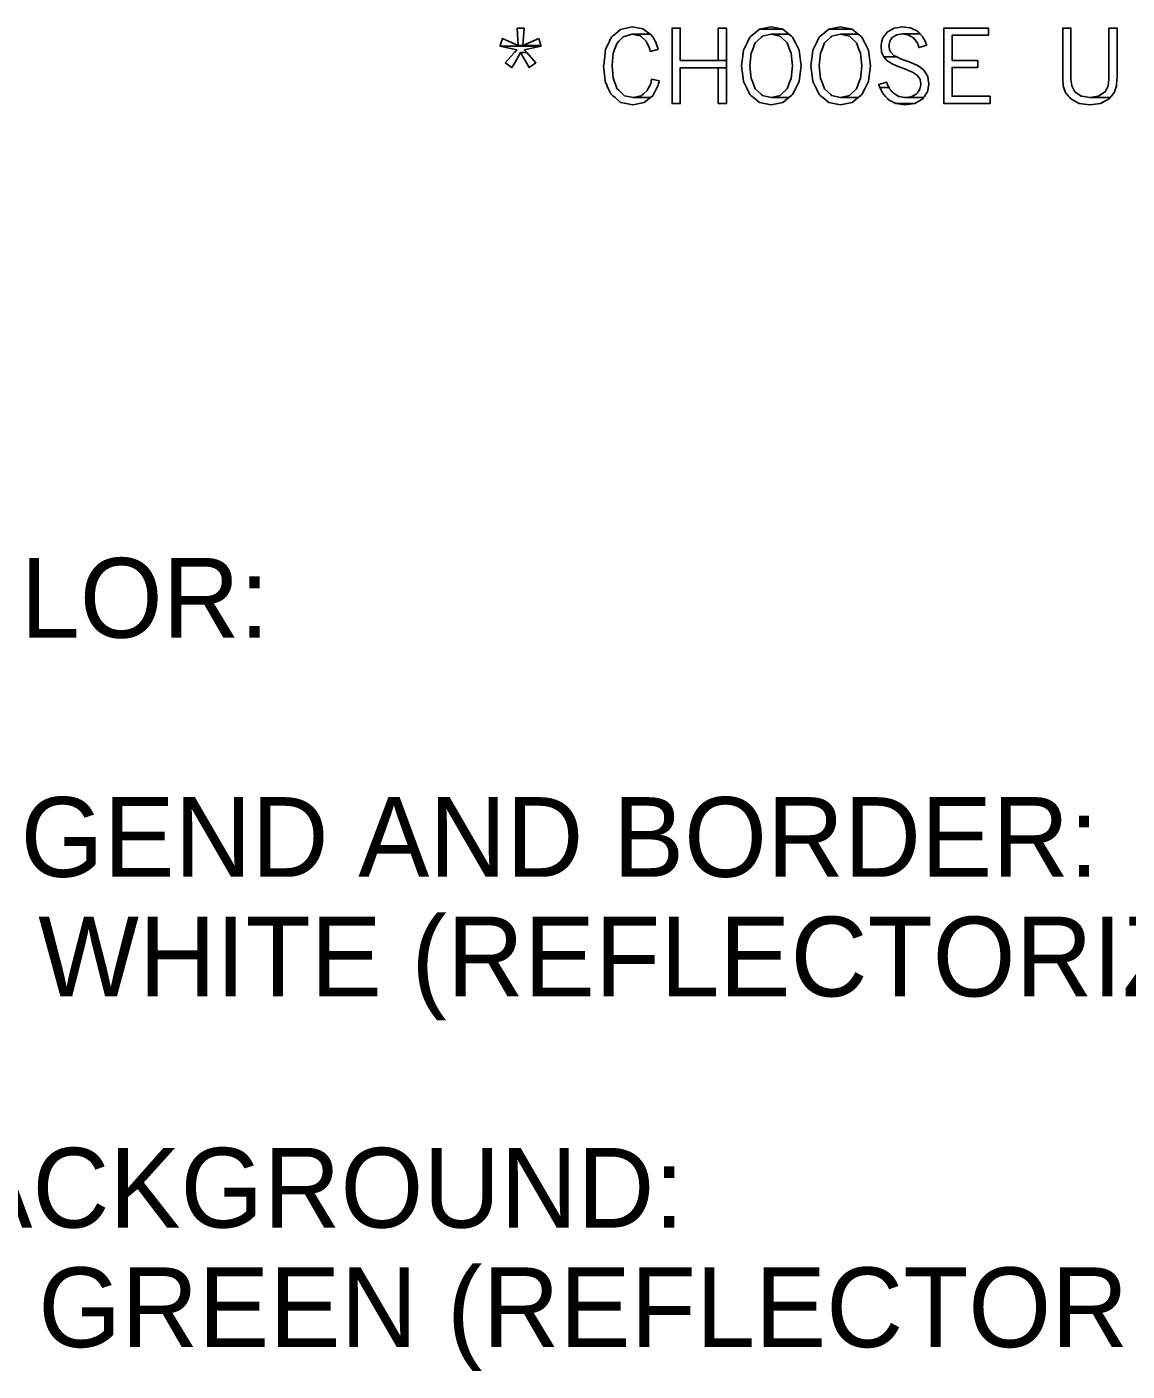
# Model space of a CAD drawing. Extents: x 0.011 to 0.188, y 0.004 to 0.261.
# Drawn here: x 0.02906 to 0.06383, y 0.00969 to 0.05218 of the extents above; entities that cross this region are included whole.
import ezdxf

# ---------------------------------------------------------------- set-up
doc = ezdxf.new("R2010")
doc.units = 0
doc.layers.add('1', color=7, linetype='Continuous')
doc.layers.add('3', color=7, linetype='Continuous')

msp = doc.modelspace()

# ---------------------------------------------------------------- linework, layer by layer
at = {"layer": '3'}
for points in [[(0.044549, 0.052147), (0.044588, 0.051595), (0.044733, 0.051595), (0.044771, 0.052147)], [(0.047835, 0.049793), (0.048203, 0.049722), (0.048567, 0.049793), (0.048571, 0.049796), (0.048762, 0.049949), (0.048214, 0.049949), (0.047947, 0.050008), (0.047943, 0.050009), (0.047942, 0.05001), (0.047942, 0.05001), (0.047884, 0.050067), (0.047883, 0.050067), (0.047777, 0.050173), (0.047707, 0.050241), (0.047682, 0.050312), (0.047651, 0.050394), (0.04763, 0.050451), (0.047621, 0.050476), (0.047587, 0.050569), (0.047556, 0.050953), (0.047554, 0.050976), (0.047591, 0.051357), (0.04761, 0.05141), (0.04763, 0.051469), (0.047632, 0.051474), (0.047656, 0.05154), (0.047699, 0.051659), (0.047721, 0.051682), (0.04777, 0.051733), (0.0479, 0.051869), (0.047906, 0.051875), (0.048004, 0.051905), (0.048074, 0.051926), (0.048074, 0.051926), (0.048182, 0.051959), (0.048755, 0.051959), (0.048555, 0.052105), (0.048555, 0.052105), (0.048526, 0.052126), (0.048184, 0.052185), (0.048184, 0.052185), (0.047917, 0.052126), (0.04782, 0.052105), (0.047645, 0.051959), (0.047606, 0.051926), (0.047581, 0.051905), (0.047545, 0.051875), (0.047538, 0.051869), (0.047472, 0.051733), (0.047448, 0.051682), (0.047436, 0.051659), (0.047378, 0.05154), (0.047346, 0.051474), (0.047344, 0.051469), (0.047337, 0.05141), (0.047331, 0.051357), (0.047288, 0.050976), (0.047285, 0.050953), (0.047325, 0.050569), (0.047335, 0.050476), (0.047338, 0.050451), (0.047364, 0.050394), (0.0474, 0.050312), (0.047432, 0.050241), (0.047462, 0.050173), (0.04751, 0.050067), (0.047575, 0.05001), (0.047577, 0.050009), (0.047578, 0.050008), (0.047645, 0.049949), (0.04782, 0.049796)], [(0.048742, 0.051469), (0.048757, 0.05141), (0.048985, 0.051469), (0.049006, 0.051474), (0.048986, 0.05154), (0.048986, 0.05154), (0.04895, 0.051659), (0.048944, 0.051682), (0.048914, 0.051733), (0.048835, 0.051869), (0.048834, 0.051869), (0.048831, 0.051875), (0.048813, 0.051905), (0.048801, 0.051926), (0.048755, 0.051959), (0.048182, 0.051959), (0.048339, 0.051926), (0.048442, 0.051905), (0.048474, 0.051875), (0.048481, 0.051869), (0.04863, 0.051733), (0.048654, 0.051682), (0.048665, 0.051659), (0.048724, 0.05154), (0.048741, 0.051474)], [(0.049448, 0.050894), (0.049448, 0.04976), (0.049707, 0.04976), (0.049707, 0.050894), (0.051166, 0.050894), (0.051166, 0.051126), (0.049707, 0.051126), (0.049707, 0.052147), (0.049448, 0.052147), (0.049448, 0.051126)], [(0.050906, 0.052147), (0.050906, 0.051126), (0.051166, 0.051126), (0.051166, 0.052147)], [(0.052211, 0.049798), (0.052582, 0.049721), (0.052953, 0.049798), (0.053142, 0.049951), (0.052581, 0.049951), (0.0523, 0.050015), (0.052271, 0.050043), (0.052078, 0.050227), (0.051988, 0.050455), (0.051948, 0.050556), (0.051906, 0.050953), (0.051948, 0.05135), (0.051988, 0.051451), (0.052078, 0.051679), (0.052271, 0.051863), (0.0523, 0.051891), (0.052581, 0.051956), (0.053142, 0.051956), (0.052953, 0.052108), (0.052211, 0.052108), (0.052022, 0.051956), (0.051942, 0.051891), (0.051908, 0.051863), (0.051817, 0.051679), (0.051704, 0.051451), (0.051691, 0.05135), (0.051639, 0.050953), (0.051691, 0.050556), (0.051704, 0.050455), (0.051817, 0.050227), (0.051908, 0.050043), (0.051942, 0.050015), (0.052022, 0.049951)], [(0.052582, 0.052185), (0.052211, 0.052108), (0.052953, 0.052108)], [(0.052863, 0.050015), (0.052581, 0.049951), (0.053142, 0.049951), (0.053222, 0.050015), (0.053222, 0.050015), (0.053256, 0.050043), (0.053347, 0.050227), (0.05346, 0.050455), (0.053473, 0.050556), (0.053525, 0.050953), (0.053473, 0.05135), (0.05346, 0.051451), (0.053347, 0.051679), (0.053256, 0.051863), (0.053222, 0.051891), (0.053222, 0.051891), (0.053142, 0.051956), (0.052581, 0.051956), (0.052863, 0.051891), (0.052892, 0.051863), (0.053084, 0.051679), (0.053174, 0.051451), (0.053214, 0.05135), (0.053256, 0.050953), (0.053214, 0.050556), (0.053174, 0.050455), (0.053084, 0.050227), (0.052892, 0.050043)], [(0.054402, 0.049798), (0.054773, 0.049721), (0.055145, 0.049798), (0.055333, 0.049951), (0.054773, 0.049951), (0.054491, 0.050015), (0.054462, 0.050043), (0.05427, 0.050227), (0.054179, 0.050455), (0.05414, 0.050556), (0.054098, 0.050953), (0.05414, 0.05135), (0.054179, 0.051451), (0.05427, 0.051679), (0.054462, 0.051863), (0.054491, 0.051891), (0.054773, 0.051956), (0.055333, 0.051956), (0.055145, 0.052108), (0.054402, 0.052108), (0.054213, 0.051956), (0.054133, 0.051891), (0.054099, 0.051863), (0.054008, 0.051679), (0.053895, 0.051451), (0.053882, 0.05135), (0.05383, 0.050953), (0.053882, 0.050556), (0.053895, 0.050455), (0.054008, 0.050227), (0.054099, 0.050043), (0.054133, 0.050015), (0.054213, 0.049951)], [(0.054773, 0.052185), (0.054402, 0.052108), (0.055145, 0.052108)], [(0.055054, 0.050015), (0.054773, 0.049951), (0.055333, 0.049951), (0.055414, 0.050015), (0.055413, 0.050015), (0.055448, 0.050043), (0.055539, 0.050227), (0.055652, 0.050455), (0.055665, 0.050556), (0.055716, 0.050953), (0.055665, 0.05135), (0.055652, 0.051451), (0.055539, 0.051679), (0.055448, 0.051863), (0.055414, 0.051891), (0.055413, 0.051891), (0.055333, 0.051956), (0.054772, 0.051956), (0.055054, 0.051891), (0.055083, 0.051863), (0.055276, 0.051679), (0.055366, 0.051451), (0.055406, 0.05135), (0.055448, 0.050953), (0.055406, 0.050556), (0.055366, 0.050455), (0.055276, 0.050227), (0.055083, 0.050043)], [(0.056115, 0.051283), (0.056138, 0.051233), (0.056553, 0.051233), (0.056456, 0.051283), (0.056367, 0.051388), (0.056335, 0.051427), (0.056312, 0.051533), (0.056303, 0.051574), (0.056307, 0.051602), (0.056311, 0.051624), (0.05632, 0.051674), (0.05632, 0.05168), (0.056329, 0.051728), (0.056398, 0.051834), (0.056411, 0.051852), (0.056422, 0.051859), (0.056438, 0.051869), (0.056548, 0.051936), (0.05655, 0.051937), (0.056721, 0.051964), (0.057279, 0.051964), (0.057221, 0.052026), (0.057201, 0.052047), (0.057, 0.052143), (0.056969, 0.052158), (0.056714, 0.052185), (0.056714, 0.052185), (0.056557, 0.052158), (0.056468, 0.052143), (0.056296, 0.052047), (0.056258, 0.052026), (0.056207, 0.051964), (0.056185, 0.051937), (0.056184, 0.051936), (0.056129, 0.051869), (0.056121, 0.051859), (0.056119, 0.051852), (0.056114, 0.051834), (0.056082, 0.051728), (0.056068, 0.05168), (0.056067, 0.051674), (0.056052, 0.051624), (0.056053, 0.051602), (0.056055, 0.051574), (0.056058, 0.051533), (0.056065, 0.051427), (0.056068, 0.051388)], [(0.05724, 0.051574), (0.057256, 0.051533), (0.057397, 0.051574), (0.057493, 0.051602), (0.057486, 0.051624), (0.057471, 0.051674), (0.057469, 0.05168), (0.057443, 0.051728), (0.057388, 0.051834), (0.057378, 0.051852), (0.057375, 0.051859), (0.05737, 0.051869), (0.057306, 0.051936), (0.057305, 0.051937), (0.057279, 0.051964), (0.05672, 0.051964), (0.056892, 0.051937), (0.056902, 0.051936), (0.057021, 0.051869), (0.057039, 0.051859), (0.057051, 0.051852), (0.057083, 0.051834), (0.057161, 0.051728), (0.057197, 0.05168), (0.057202, 0.051674), (0.057221, 0.051624), (0.057229, 0.051602)], [(0.058038, 0.04999), (0.058038, 0.04976), (0.059501, 0.04976), (0.059501, 0.04999), (0.0583, 0.04999), (0.0583, 0.050903), (0.059111, 0.050903), (0.059111, 0.051124), (0.0583, 0.051124), (0.0583, 0.051921), (0.059445, 0.051921), (0.059445, 0.052147), (0.058038, 0.052147), (0.058038, 0.051921), (0.058038, 0.051124), (0.058038, 0.050903)], [(0.062314, 0.049767), (0.062653, 0.049722), (0.062992, 0.049767), (0.06326, 0.04991), (0.063291, 0.049948), (0.062653, 0.049948), (0.062395, 0.049993), (0.062378, 0.049996), (0.062213, 0.050108), (0.062179, 0.050131), (0.062177, 0.050132), (0.062078, 0.050324), (0.062078, 0.050326), (0.062077, 0.050331), (0.062077, 0.050332), (0.062055, 0.050524), (0.062054, 0.050564), (0.062054, 0.050567), (0.062054, 0.050652), (0.062054, 0.052147), (0.061794, 0.052147), (0.061794, 0.050652), (0.061794, 0.050567), (0.061794, 0.050564), (0.061797, 0.050524), (0.061809, 0.050332), (0.061809, 0.050331), (0.06181, 0.050326), (0.061811, 0.050324), (0.061875, 0.050132), (0.061875, 0.050131), (0.061883, 0.050108), (0.061975, 0.049996), (0.061978, 0.049993), (0.062015, 0.049948), (0.062046, 0.04991)], [(0.062924, 0.049993), (0.062653, 0.049948), (0.063291, 0.049948), (0.063328, 0.049993), (0.063331, 0.049996), (0.063423, 0.050108), (0.063431, 0.050131), (0.063431, 0.050132), (0.063496, 0.050324), (0.063495, 0.050324), (0.063496, 0.050326), (0.063496, 0.050326), (0.063498, 0.050331), (0.063498, 0.050332), (0.063509, 0.050524), (0.063512, 0.050564), (0.063512, 0.050567), (0.063512, 0.050652), (0.063512, 0.052147), (0.063253, 0.052147), (0.063253, 0.050652), (0.063252, 0.050567), (0.063252, 0.050564), (0.063252, 0.050524), (0.063232, 0.050332), (0.063232, 0.050331), (0.063231, 0.050326), (0.06323, 0.050324), (0.063133, 0.050132), (0.063132, 0.050131), (0.063097, 0.050108), (0.062928, 0.049996)], [(0.044016, 0.051595), (0.04401, 0.051577), (0.04531, 0.051577), (0.045304, 0.051595), (0.044588, 0.051595), (0.044087, 0.051818)], [(0.044175, 0.05105), (0.044384, 0.050896), (0.044474, 0.05105), (0.044662, 0.051371), (0.044855, 0.051371), (0.044778, 0.051457), (0.04531, 0.051577), (0.04401, 0.051577), (0.044543, 0.051457), (0.044465, 0.051371)], [(0.045234, 0.051818), (0.044733, 0.051595), (0.045304, 0.051595)], [(0.044847, 0.05105), (0.044937, 0.050896), (0.045145, 0.05105), (0.044856, 0.051371), (0.044662, 0.051371)], [(0.057003, 0.049974), (0.056811, 0.049949), (0.057399, 0.049949), (0.057415, 0.049974), (0.057422, 0.049984), (0.057468, 0.050054), (0.057478, 0.050069), (0.057478, 0.050069), (0.05749, 0.050087), (0.057522, 0.050136), (0.057532, 0.050191), (0.057538, 0.050224), (0.057544, 0.050264), (0.057559, 0.050349), (0.057561, 0.050359), (0.057562, 0.050364), (0.057565, 0.050381), (0.057544, 0.05052), (0.05753, 0.050616), (0.05751, 0.050648), (0.057448, 0.050751), (0.057406, 0.050819), (0.057383, 0.050836), (0.057253, 0.050931), (0.057209, 0.050963), (0.057085, 0.051016), (0.056966, 0.051068), (0.056845, 0.051111), (0.056663, 0.051177), (0.056553, 0.051233), (0.056138, 0.051233), (0.05619, 0.051177), (0.056251, 0.051111), (0.056319, 0.051068), (0.0564, 0.051016), (0.056522, 0.050963), (0.056595, 0.050931), (0.056853, 0.050836), (0.056892, 0.050819), (0.05705, 0.050751), (0.057204, 0.050648), (0.057224, 0.050616), (0.057286, 0.05052), (0.057307, 0.050381), (0.057309, 0.050364), (0.057308, 0.050359), (0.057306, 0.050349), (0.057288, 0.050264), (0.05728, 0.050224), (0.057273, 0.050191), (0.057228, 0.050136), (0.057189, 0.050087), (0.057173, 0.050069), (0.057162, 0.050054), (0.057023, 0.049984)], [(0.050906, 0.050894), (0.050906, 0.04976), (0.051166, 0.04976), (0.051166, 0.050894)], [(0.048472, 0.050008), (0.048214, 0.049949), (0.048762, 0.049949), (0.048836, 0.050008), (0.048837, 0.050009), (0.048837, 0.050009), (0.048839, 0.05001), (0.048868, 0.050067), (0.048923, 0.050173), (0.048959, 0.050241), (0.048996, 0.050312), (0.049019, 0.050394), (0.049036, 0.050451), (0.049043, 0.050476), (0.048804, 0.050529), (0.048791, 0.050476), (0.048785, 0.050451), (0.048772, 0.050394), (0.048731, 0.050312), (0.048697, 0.050241), (0.048664, 0.050173), (0.048541, 0.050067), (0.048474, 0.05001), (0.048473, 0.050009)], [(0.055985, 0.050349), (0.056016, 0.050264), (0.056304, 0.050264), (0.05626, 0.050349), (0.056257, 0.050359), (0.056255, 0.050364), (0.05625, 0.050381), (0.056249, 0.050381), (0.056231, 0.050439), (0.056231, 0.050439), (0.05605, 0.050381), (0.055998, 0.050364), (0.055981, 0.050359)], [(0.056293, 0.049882), (0.056523, 0.049765), (0.057119, 0.049765), (0.057317, 0.049882), (0.057379, 0.049918), (0.057399, 0.049949), (0.056811, 0.049949), (0.056669, 0.049974), (0.056669, 0.049974), (0.056613, 0.049984), (0.056498, 0.050054), (0.056475, 0.050069), (0.056445, 0.050087), (0.056402, 0.050136), (0.056353, 0.050191), (0.056353, 0.050191), (0.056324, 0.050224), (0.056304, 0.050264), (0.056015, 0.050264), (0.056036, 0.050224), (0.056053, 0.050191), (0.056081, 0.050136), (0.056107, 0.050087), (0.056117, 0.050069), (0.05613, 0.050054), (0.056196, 0.049984), (0.056206, 0.049974), (0.05623, 0.049949), (0.056258, 0.049918)], [(0.056527, 0.049764), (0.056805, 0.049721), (0.057118, 0.049764), (0.057119, 0.049765), (0.056522, 0.049765)]]:
    msp.add_lwpolyline(points, close=True, dxfattribs=at)

# ---------------------------------------------------------------- texts
at = {"layer": '1'}
for s, height, p in [('COLOR:', 0.0025197, (0.023801, 0.032876)), (' LEGEND AND BORDER:', 0.00251975, (0.023801, 0.025316)), ('      WHITE (REFLECTORIZED)', 0.00251975, (0.023801, 0.021536)), (' BACKGROUND:', 0.00251975, (0.023801, 0.014228)), ('      GREEN (REFLECTORIZED)', 0.00251975, (0.023801, 0.010448))]:
    msp.add_text(s, height=height, dxfattribs=at).set_placement(p)

doc.saveas('drawing.dxf')
